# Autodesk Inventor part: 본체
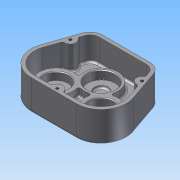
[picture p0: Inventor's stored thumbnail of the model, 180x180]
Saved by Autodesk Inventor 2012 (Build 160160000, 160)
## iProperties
Created: 2014-12
Part Number: 본체
Material: Default
Document SubType Name: Modeling
Designer: User11
Density: 1 g/cm^3
Author: User11
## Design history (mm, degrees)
sketch "스케치1"
  geometry: L1 (-47, 36)-(47, 36); L2 (47, 36)-(66.565, -20.803); L3 (-47, 36)-(-66.565, -20.803); L4 (-32.527, -68.527)-(32.527, -68.527); L5 (-32.527, -32.527)-(0, 0); L6 (0, 0)-(32.527, -32.527); A1 r 36 centre (-32.527, -32.527) between (-66.565, -20.803) and (-32.527, -68.527); A2 r 36 centre (32.527, -32.527) between (32.527, -68.527) and (66.565, -20.803)
  constraints: 12 end point, 4 point on circle, 4 tangent, 2 centre point, 2 horizontal, 1 equal length, 1 horizontal alignment
  dimensions: "d0" = 36 distance from line of L5.end L1; "d1" = 47 horizontal distance of L5.end L1.start; "d2" = 94 distance of L1.start L1.end; "d3" = 36 radius of A2; "d4" = 90 deg angle of L6 L5; "d6" = 46 distance of L5.start L5.end
extrude "돌출1" new body sketch "스케치1" distance "d7" = 44; taper "d8" = 0 deg
fillet "모깎기1" dims "d9" = 18
feature "쉘1" dims "d10" = 5
feature "두껍게 하기1" dims "d11" = 5, "d12" = 5
sketch "스케치2"
  geometry: A1 r 31 centre (1.635, -63.527) between (-27.675, -53.432) and (1.635, -94.527) reference; A2 r 31 centre (66.689, -63.527) between (66.689, -94.527) and (95.999, -53.432) reference; A3 r 24 centre (1.635, -63.527) between (13.051, -42.416) and (22.746, -52.111); A4 r 24 centre (66.689, -63.527) between (45.578, -52.111) and (55.273, -42.416); A5 r 24 centre (34.162, -31) between (22.746, -52.111) and (45.578, -52.111); A6 r 24 centre (34.162, -31) between (55.273, -42.416) and (13.051, -42.416); 1 further point
  constraints: 8 point on circle, 4 centre point, 3 coincident, 1 concentric
  dimensions: "d14" = 48 diameter of A3; "d15" = 48 diameter of A4; "d16" = 24 radius of A6
extrude "돌출2" join sketch "스케치2" distance "d17" = 11; taper "d18" = 0 deg
sketch "스케치3"
  geometry: C1 r 20 at (-32.527, -32.527); C2 r 20 at (32.527, -32.527); A1 r 36 centre (-32.527, -32.527) between (-66.565, -20.803) and (-32.527, -68.527) reference; A2 r 36 centre (32.527, -32.527) between (32.527, -68.527) and (66.565, -20.803) reference; 1 further point
  constraints: 2 centre point, 2 coincident, 1 equal radius
  dimensions: "d19" = 40 diameter of C1
extrude "돌출3" join sketch "스케치3" distance "d20" = 7; taper "d21" = -10 deg
sketch "스케치4"
  geometry: L1 (46.453, 22.233)-(61.837, -22.432) reference; L2 (32.527, -63.527)-(-32.527, -63.527) reference; L3 (-61.837, -22.432)-(-46.453, 22.233) reference; L4 (-34.162, 36)-(34.162, 36) reference; L5 (-61.837, -22.432)-(-46.453, 22.233) reference; L6 (-34.162, 31)-(34.162, 31) reference; A1 r 8 centre (-51.7, 7) between (-54.305, -0.564) and (-49.095, 14.564); A2 r 8 centre (51.7, 7) between (49.095, 14.564) and (54.305, -0.564); A3 r 8 centre (0, -63.527) between (8, -63.527) and (-8, -63.527); 2 further points
  constraints: 8 point on line, 6 point on circle, 3 centre point, 2 equal radius, 2 midpoint, 2 vertical alignment, 1 horizontal alignment
  dimensions: "d22" = 16 diameter of A1; "d23" = 29 distance from line of A1.centre L4
extrude "돌출4" join sketch "스케치4" stored distance "d24" = 7; taper "d25" = 0 deg
extrude "돌출5" join sketch "스케치4" stored distance "d26" = 7; taper "d27" = 0 deg
extrude "돌출6" join sketch "스케치4" stored distance "d28" = 7; taper "d29" = 0 deg
fillet "모깎기2" dims "d30" = 3
fillet "모깎기3" dims "d31" = 3
hole "구멍1" diameter "d34" = 15.5; stored, may be unused: countersink angle "d38" = 90 deg, drill point angle "d40" = 118 deg; dims "d32" = 10, "d33" = 10, "d35" = 6, "d36" = 4, "d37" = 2, "d39" = 8
hole "구멍2" diameter "d43" = 15.5; stored, may be unused: countersink angle "d47" = 90 deg, drill point angle "d49" = 118 deg; dims "d41" = 10, "d42" = 10, "d44" = 6, "d45" = 4, "d46" = 2, "d48" = 8
hole "구멍3" diameter "d52" = 35; stored, may be unused: countersink angle "d56" = 90 deg, drill point angle "d58" = 0 deg; dims "d50" = 10, "d51" = 10, "d53" = 6, "d54" = 4, "d55" = 2, "d57" = 11
hole "구멍4" diameter "d61" = 35; stored, may be unused: countersink angle "d65" = 90 deg, drill point angle "d67" = 0 deg; dims "d62" = 6, "d63" = 4, "d64" = 2, "d66" = 11, "d68" = 10, "d69" = 10
hole "구멍5" diameter "d72" = 30; stored, may be unused: countersink angle "d76" = 90 deg, drill point angle "d78" = 0 deg; dims "d70" = 10, "d71" = 10, "d73" = 6, "d74" = 4, "d75" = 2, "d77" = 7
hole "구멍6" diameter "d81" = 30; stored, may be unused: countersink angle "d85" = 90 deg, drill point angle "d87" = 0 deg; dims "d82" = 6, "d83" = 4, "d84" = 2, "d86" = 7, "d88" = 10, "d89" = 10
hole "구멍7" diameter "d92" = 40; stored, may be unused: countersink angle "d96" = 90 deg, drill point angle "d98" = 0 deg; dims "d90" = 10, "d91" = 10, "d93" = 6, "d94" = 4, "d95" = 2, "d97" = 12
hole "구멍8" diameter "d101" = 20; stored, may be unused: countersink angle "d105" = 90 deg, drill point angle "d107" = 0 deg; dims "d99" = 10, "d100" = 10, "d102" = 6, "d103" = 4, "d104" = 2, "d106" = 3
chamfer "모따기1" distance "d108" = 1; stored, may be unused: second distance "d109" = 2, angle "d110" = 45 deg
fillet "모깎기4" dims "d111" = 0.3, "d112" = 0.1, "d113" = 3
hole "구멍9" diameter "d116" = 4.134; stored, may be unused: countersink angle "d120" = 90 deg, drill point angle "d122" = 118 deg; dims "d114" = 10, "d115" = 10, "d117" = 20, "d118" = 4, "d119" = 2, "d121" = 23
hole "구멍10" diameter "d125" = 4.134; stored, may be unused: countersink angle "d129" = 90 deg, drill point angle "d131" = 118 deg; dims "d123" = 10, "d124" = 10, "d126" = 20, "d127" = 4, "d128" = 2, "d130" = 23
hole "구멍11" diameter "d134" = 4.134; stored, may be unused: countersink angle "d138" = 90 deg, drill point angle "d140" = 118 deg; dims "d132" = 10, "d133" = 10, "d135" = 20, "d136" = 4, "d137" = 2, "d139" = 23
sketch "스케치5"
  geometry: L1 (34.162, 36)-(-34.162, 36) reference; 2 further points
  constraints: 1 vertical alignment, 1 other
  dimensions: "d141" = 30 distance from line of L1 point (0, 6)
feature "엠보싱1" sketch "스케치5" dims "d0" = 36, "d1" = 47, "d2" = 94, "d3" = 36, "d4" = 90 deg, "d6" = 46, "d142" = 1, "d143" = 0
node "솔리드1"
other parameters: "d13" = 48
